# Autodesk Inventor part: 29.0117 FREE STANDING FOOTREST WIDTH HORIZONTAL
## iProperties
Created: 2007-06
Part Number: 29.0117 FREE STANDING FOOTREST WIDTH HORIZONTAL
Material: Aluminum-6061
Document SubType Name: Modeling
Designer: Andy Moles
Density: 2.71 g/cm^3
Author: Andy Moles
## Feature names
1. Extrusion1
